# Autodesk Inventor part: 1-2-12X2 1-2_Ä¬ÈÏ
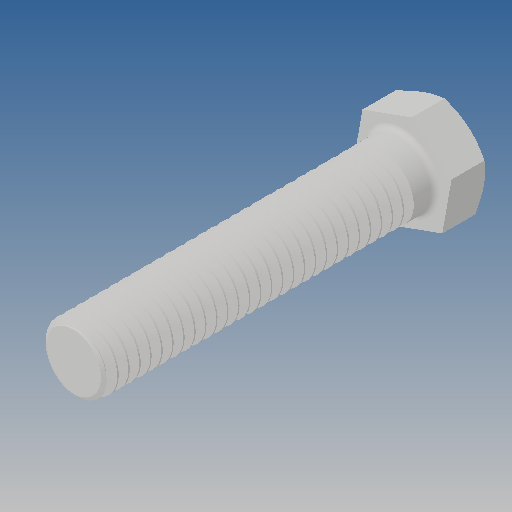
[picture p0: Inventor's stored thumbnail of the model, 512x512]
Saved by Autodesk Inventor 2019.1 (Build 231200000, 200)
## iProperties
Created: 2010-06
Part Number: 1-2-12X2 1-2_Ä¬ÈÏ
Material: Ogólny
Document SubType Name: Modeling
Designer: CADENGINEERING4
Density: 1 g/cm^3
Appearance: Domyślna
Author: CADENGINEERING4
Revision Number: ÈÎºÎ
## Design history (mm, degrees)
feature "NONE"
node "Bryła1"
